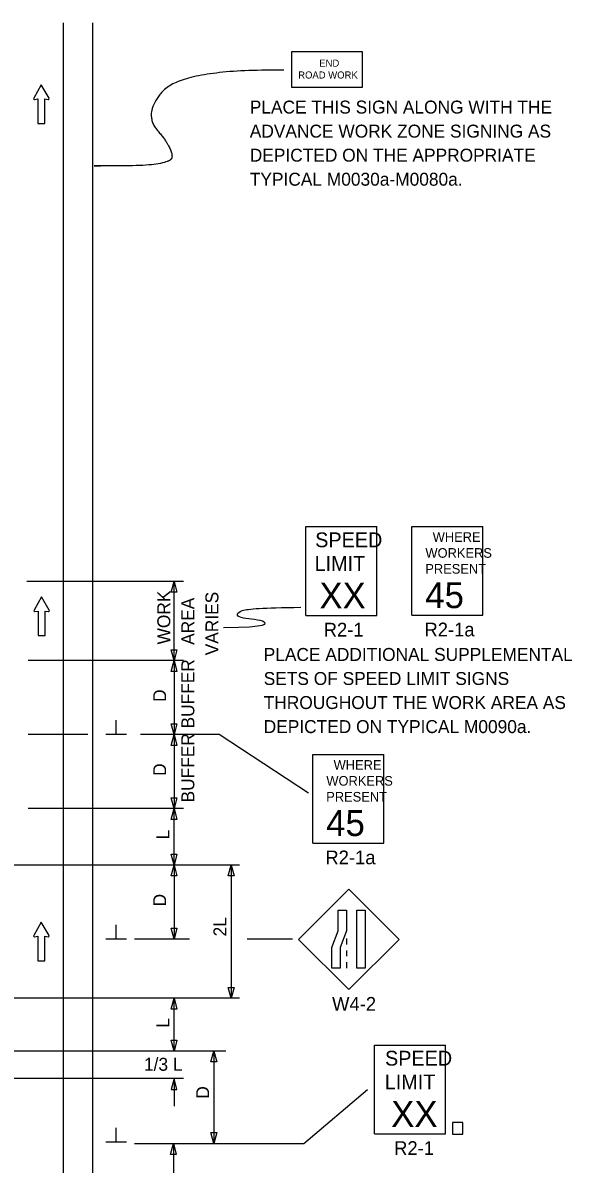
# Model space of a CAD drawing. Extents: x 16724 to 18475, y 5726 to 6929.
# Drawn here: x 17124 to 17420, y 6308 to 6925 of the extents above; entities that cross this region are included whole.
import ezdxf

# ---------------------------------------------------------------- set-up
doc = ezdxf.new("R2010")
doc.units = 0
for name, color, linetype in [('Level 3', 7, 'Continuous'), ('MT_SCRATCH_LEVEL_E', 7, 'Continuous'), ('PAVT_EDGE_EX', 7, 'Continuous'), ('TRAFFIC_SIGNS_PR', 7, 'Continuous'), ('TYPICAL_TEXT_DIMEN_PR', 7, 'Continuous')]:
    doc.layers.add(name, color=color, linetype=linetype)

msp = doc.modelspace()

# ---------------------------------------------------------------- linework, layer by layer
at = {"layer": 'Level 3'}
msp.add_line((17275.52, 6318.89), (17309.79, 6348.05), dxfattribs=at)
at = {"layer": 'MT_SCRATCH_LEVEL_E'}
for p, q in [((17133.63, 6891.21), (17129.52, 6883.97)), ((17133.63, 6891.21), (17129.52, 6883.97)), ((17137.78, 6883.97), (17133.63, 6891.21)), ((17137.78, 6883.97), (17133.63, 6891.21)), ((17130, 6883.28), (17131.78, 6883.6)), ((17130, 6883.28), (17131.78, 6883.6)), ((17131.78, 6883.6), (17131.78, 6870.34)), ((17131.78, 6883.6), (17131.78, 6870.34)), ((17135.52, 6870.34), (17135.52, 6883.6)), ((17135.52, 6883.6), (17137.3, 6883.28)), ((17135.52, 6870.34), (17135.52, 6883.6)), ((17135.52, 6883.6), (17137.3, 6883.28)), ((17131.78, 6870.34), (17135.52, 6870.34)), ((17131.78, 6870.34), (17135.52, 6870.34)), ((17133.8, 6614.38), (17129.68, 6607.14)), ((17133.8, 6614.38), (17129.68, 6607.14)), ((17137.94, 6607.14), (17133.8, 6614.38)), ((17137.94, 6607.14), (17133.8, 6614.38)), ((17130.17, 6606.46), (17131.94, 6606.77)), ((17130.17, 6606.46), (17131.94, 6606.77)), ((17131.94, 6606.77), (17131.94, 6593.51)), ((17131.94, 6606.77), (17131.94, 6593.51)), ((17135.69, 6593.51), (17135.69, 6606.77)), ((17135.69, 6606.77), (17137.46, 6606.46)), ((17135.69, 6593.51), (17135.69, 6606.77)), ((17135.69, 6606.77), (17137.46, 6606.46)), ((17131.94, 6593.51), (17135.69, 6593.51)), ((17131.94, 6593.51), (17135.69, 6593.51)), ((17133.63, 6438.6), (17129.52, 6431.36)), ((17133.63, 6438.6), (17129.52, 6431.36)), ((17137.78, 6431.36), (17133.63, 6438.6)), ((17137.78, 6431.36), (17133.63, 6438.6)), ((17130, 6430.67), (17131.78, 6430.99)), ((17130, 6430.67), (17131.78, 6430.99)), ((17131.78, 6430.99), (17131.78, 6417.73)), ((17131.78, 6430.99), (17131.78, 6417.73)), ((17135.52, 6417.73), (17135.52, 6430.99)), ((17135.52, 6430.99), (17137.3, 6430.67)), ((17135.52, 6417.73), (17135.52, 6430.99)), ((17135.52, 6430.99), (17137.3, 6430.67)), ((17131.78, 6417.73), (17135.52, 6417.73)), ((17131.78, 6417.73), (17135.52, 6417.73))]:
    msp.add_line(p, q, dxfattribs=at)
for centre, start, end in [((17129.93, 6883.74), 150.42484, 279.96381), ((17129.93, 6883.74), 150.42484, 279.96381), ((17137.37, 6883.74), 260.03619, 29.77312), ((17137.37, 6883.74), 260.03619, 29.77312), ((17130.09, 6606.92), 150.42484, 279.96381), ((17130.09, 6606.92), 150.42484, 279.96381), ((17137.53, 6606.92), 260.03619, 29.77312), ((17137.53, 6606.92), 260.03619, 29.77312), ((17129.93, 6431.13), 150.42484, 279.96381), ((17129.93, 6431.13), 150.42484, 279.96381), ((17137.37, 6431.13), 260.03619, 29.77312), ((17137.37, 6431.13), 260.03619, 29.77312)]:
    msp.add_arc(centre, 0.463, start, end, dxfattribs=at)
at = {"layer": 'PAVT_EDGE_EX'}
for p, q in [((17145.36, 6924.76), (17145.36, 6059.7)), ((17161.36, 6924.76), (17161.36, 6059.7))]:
    msp.add_line(p, q, dxfattribs=at)
at = {"layer": 'TRAFFIC_SIGNS_PR'}
for p, q in [((17276.58, 6652.39), (17314.98, 6652.39)), ((17276.58, 6604.39), (17276.58, 6652.39)), ((17314.98, 6604.39), (17314.98, 6652.39)), ((17333.78, 6652.48), (17372.18, 6652.48)), ((17333.78, 6604.48), (17333.78, 6652.48)), ((17372.18, 6604.48), (17372.18, 6652.48)), ((17276.58, 6604.39), (17314.98, 6604.39)), ((17333.78, 6604.48), (17372.18, 6604.48)), ((17280.25, 6529.27), (17318.65, 6529.27)), ((17280.25, 6481.27), (17280.25, 6529.27)), ((17318.65, 6481.27), (17318.65, 6529.27)), ((17280.25, 6481.27), (17318.65, 6481.27)), ((17299.77, 6456.38), (17272.61, 6429.23)), ((17326.92, 6429.23), (17299.77, 6456.38)), ((17298.52, 6429.72), (17298.52, 6426.52)), ((17272.61, 6429.23), (17299.77, 6402.08)), ((17299.77, 6402.08), (17326.92, 6429.23)), ((17298.52, 6423.32), (17298.52, 6420.12)), ((17298.52, 6416.92), (17298.52, 6413.72)), ((17313.57, 6372.12), (17351.97, 6372.12)), ((17313.57, 6324.12), (17313.57, 6372.12)), ((17351.97, 6324.12), (17351.97, 6372.12)), ((17313.57, 6324.12), (17351.97, 6324.12))]:
    msp.add_line(p, q, dxfattribs=at)
for points in [[(17268.81, 6889.91), (17307.21, 6889.91), (17307.21, 6909.11), (17268.81, 6909.11)], [(17298.52, 6444.97), (17298.52, 6433.79), (17295.18, 6424.9), (17295.18, 6413.72), (17290.68, 6413.72), (17290.68, 6424.9), (17294.03, 6433.79), (17294.03, 6444.97)], [(17308.66, 6444.97), (17308.66, 6413.72), (17304.16, 6413.72), (17304.16, 6444.97)], [(17355.85, 6324.01), (17361.44, 6324.01), (17361.44, 6330.18), (17355.85, 6330.18)]]:
    msp.add_lwpolyline(points, close=True, dxfattribs=at)
at = {"layer": 'TYPICAL_TEXT_DIMEN_PR'}
for p, q in [((17210.36, 6622.81), (17125.86, 6622.81)), ((17203.79, 6616.95), (17205.36, 6622.81)), ((17205.36, 6579.97), (17205.36, 6622.81)), ((17205.36, 6622.81), (17206.93, 6616.95)), ((17205.36, 6616.95), (17203.79, 6616.95)), ((17206.93, 6616.95), (17205.36, 6616.95)), ((17205.36, 6579.97), (17203.79, 6585.83)), ((17203.79, 6585.83), (17205.36, 6585.83)), ((17205.36, 6585.83), (17206.93, 6585.83)), ((17206.93, 6585.83), (17205.36, 6579.97)), ((17210.36, 6579.97), (17126.54, 6579.97)), ((17203.79, 6574.1), (17205.36, 6579.97)), ((17205.36, 6579.97), (17205.36, 6539.97)), ((17205.36, 6579.97), (17206.93, 6574.1)), ((17205.36, 6574.1), (17203.79, 6574.1)), ((17206.93, 6574.1), (17205.36, 6574.1)), ((17174.11, 6539.97), (17174.11, 6547.75)), ((17205.36, 6539.97), (17203.79, 6545.83)), ((17203.79, 6545.83), (17205.36, 6545.83)), ((17205.36, 6545.83), (17206.93, 6545.83)), ((17206.93, 6545.83), (17205.36, 6539.97)), ((17158.71, 6539.97), (17126.54, 6539.97)), ((17179.74, 6539.97), (17168.49, 6539.97)), ((17229.73, 6539.97), (17187.19, 6539.97)), ((17203.79, 6534.1), (17205.36, 6539.97)), ((17205.36, 6539.97), (17205.36, 6499.97)), ((17205.36, 6539.97), (17206.93, 6534.1)), ((17278.05, 6508.34), (17229.73, 6539.97)), ((17205.36, 6534.1), (17203.79, 6534.1)), ((17206.93, 6534.1), (17205.36, 6534.1)), ((17205.36, 6499.97), (17203.79, 6505.83)), ((17203.79, 6505.83), (17205.36, 6505.83)), ((17205.36, 6505.83), (17206.93, 6505.83)), ((17206.93, 6505.83), (17205.36, 6499.97)), ((17210.36, 6499.97), (17126.54, 6499.97)), ((17203.79, 6494.1), (17205.36, 6499.97)), ((17205.36, 6499.97), (17206.93, 6494.1)), ((17205.36, 6469.39), (17205.36, 6499.97)), ((17205.36, 6494.1), (17203.79, 6494.1)), ((17206.93, 6494.1), (17205.36, 6494.1)), ((17205.36, 6469.39), (17203.79, 6475.25)), ((17203.79, 6475.25), (17205.36, 6475.25)), ((17205.36, 6475.25), (17206.93, 6475.25)), ((17206.93, 6475.25), (17205.36, 6469.39)), ((17240.72, 6469.39), (17104.72, 6469.39)), ((17203.79, 6463.53), (17205.36, 6469.39)), ((17205.36, 6469.39), (17205.36, 6429.39)), ((17205.36, 6469.39), (17206.93, 6463.53)), ((17234.64, 6463.53), (17236.21, 6469.39)), ((17236.21, 6469.39), (17236.21, 6397.4)), ((17236.21, 6469.39), (17237.78, 6463.53)), ((17205.36, 6463.53), (17203.79, 6463.53)), ((17206.93, 6463.53), (17205.36, 6463.53)), ((17236.21, 6463.53), (17234.64, 6463.53)), ((17237.78, 6463.53), (17236.21, 6463.53)), ((17174.11, 6429.39), (17174.11, 6437.18)), ((17205.36, 6429.39), (17203.79, 6435.25)), ((17203.79, 6435.25), (17205.36, 6435.25)), ((17205.36, 6435.25), (17206.93, 6435.25)), ((17206.93, 6435.25), (17205.36, 6429.39)), ((17179.74, 6429.39), (17168.49, 6429.39)), ((17213.65, 6429.39), (17183.99, 6429.39)), ((17269.39, 6429.39), (17244.92, 6429.39)), ((17236.21, 6397.4), (17234.64, 6403.26)), ((17234.64, 6403.26), (17236.21, 6403.26)), ((17236.21, 6403.26), (17237.78, 6403.26)), ((17237.78, 6403.26), (17236.21, 6397.4)), ((17240.72, 6397.4), (17105.14, 6397.4)), ((17203.79, 6391.54), (17205.36, 6397.4)), ((17205.36, 6368.89), (17205.36, 6397.4)), ((17205.36, 6397.4), (17206.93, 6391.54)), ((17205.36, 6391.54), (17203.79, 6391.54)), ((17206.93, 6391.54), (17205.36, 6391.54)), ((17205.36, 6368.89), (17203.79, 6374.75)), ((17203.79, 6374.75), (17205.36, 6374.75)), ((17205.36, 6374.75), (17206.93, 6374.75)), ((17206.93, 6374.75), (17205.36, 6368.89)), ((17233.26, 6368.89), (17081.31, 6368.89)), ((17225.3, 6363.03), (17226.87, 6368.89)), ((17226.87, 6368.89), (17228.44, 6363.03)), ((17226.87, 6368.89), (17226.87, 6318.89)), ((17226.87, 6363.03), (17225.3, 6363.03)), ((17228.44, 6363.03), (17226.87, 6363.03)), ((17210.36, 6353.97), (17059.58, 6353.97)), ((17205.36, 6353.97), (17203.79, 6348.11)), ((17205.36, 6353.97), (17205.36, 6339.05)), ((17206.93, 6348.11), (17205.36, 6353.97)), ((17203.79, 6348.11), (17205.36, 6348.11)), ((17205.36, 6348.11), (17206.93, 6348.11)), ((17174.11, 6319.54), (17174.11, 6327.32)), ((17179.74, 6319.54), (17168.49, 6319.54)), ((17183.99, 6318.89), (17275.52, 6318.89)), ((17203.42, 6313.03), (17204.99, 6318.89)), ((17204.99, 6318.89), (17204.99, 6278.89)), ((17204.99, 6318.89), (17206.56, 6313.03)), ((17226.87, 6318.89), (17225.3, 6324.75)), ((17225.3, 6324.75), (17226.87, 6324.75)), ((17226.87, 6324.75), (17228.44, 6324.75)), ((17228.44, 6324.75), (17226.87, 6318.89)), ((17204.99, 6313.03), (17203.42, 6313.03)), ((17206.56, 6313.03), (17204.99, 6313.03))]:
    msp.add_line(p, q, dxfattribs=at)
for points, degree in [([(17264.57, 6899.2), (17210.19, 6899.69), (17188.43, 6875.89), (17204.26, 6857.39), (17204.26, 6847.49), (17154.61, 6847.49), (17165.65, 6847.49)], 2), ([(17231.98, 6597.83), (17256.76, 6597.98), (17255.64, 6602.34), (17238.8, 6602.34), (17238.8, 6607.61), (17252.54, 6608.52), (17273.86, 6608.81)], 3)]:
    msp.add_open_spline(points, degree=degree, dxfattribs=at)

# ---------------------------------------------------------------- texts
at = {"layer": 'TRAFFIC_SIGNS_PR'}
for s, height, p in [('END', 3.831, (17283.81, 6901.04)), ('ROAD WORK', 3.831, (17272.42, 6894.65)), ('PLACE THIS SIGN ALONG WITH THE', 7, (17246.27, 6875.71)), ('ADVANCE WORK ZONE SIGNING AS', 7, (17246.27, 6862.71)), ('DEPICTED ON THE APPROPRIATE', 7, (17246.27, 6849.71)), ('TYPICAL M0030a-M0080a.', 7, (17246.27, 6836.71)), ('SPEED', 8, (17281.61, 6641.25)), ('WHERE', 5.2, (17345.09, 6644.16)), ('WORKERS', 5.2, (17341.16, 6635.56)), ('LIMIT', 8, (17281.28, 6628.45)), ('PRESENT', 5.2, (17341.09, 6626.96)), ('XX', 14.031, (17283.89, 6608.15)), ('45', 14.031, (17341.08, 6608.33)), ('R2-1', 7.44, (17286.19, 6592.95)), ('R2-1a', 7.44, (17340.63, 6593.04)), ('PLACE ADDITIONAL SUPPLEMENTAL', 7, (17253.78, 6579.78)), ('SETS OF SPEED LIMIT SIGNS', 7, (17253.78, 6566.78)), ('THROUGHOUT THE WORK AREA AS', 7, (17253.78, 6553.78)), ('DEPICTED ON TYPICAL M0090a.', 7, (17253.78, 6540.78)), ('WHERE', 5.2, (17291.56, 6520.95)), ('WORKERS', 5.2, (17287.63, 6512.35)), ('PRESENT', 5.2, (17287.56, 6503.75)), ('45', 14.031, (17287.55, 6485.12)), ('R2-1a', 7.44, (17287.1, 6469.83)), ('W4-2', 7.44, (17290.73, 6390.64)), ('SPEED', 8, (17319.34, 6360.99)), ('LIMIT', 8, (17319.17, 6348.19)), ('XX', 14.031, (17322.68, 6327.88)), ('R2-1', 7.44, (17324.25, 6312.68))]:
    msp.add_text(s, height=height, dxfattribs=at).set_placement(p)
at = {"layer": 'TYPICAL_TEXT_DIMEN_PR'}
for s, p in [('WORK', (17203.3, 6588.69)), ('VARIES', (17229.3, 6582.82)), ('AREA', (17216.3, 6588.47)), ('BUFFER', (17216.31, 6543.28)), ('D', (17201.07, 6557.64)), ('BUFFER', (17216.31, 6503.28)), ('D', (17201.07, 6517.64)), ('L', (17202.8, 6483.26)), ('D', (17201.07, 6447.06)), ('2L', (17233.65, 6430.84)), ('L', (17202.8, 6381.54)), ('D', (17224.31, 6343.11))]:
    msp.add_text(s, height=7, rotation=90, dxfattribs=at).set_placement(p)
msp.add_text('1/3 L', height=7, dxfattribs=at).set_placement((17189.09, 6358.21))

doc.saveas('drawing.dxf')
